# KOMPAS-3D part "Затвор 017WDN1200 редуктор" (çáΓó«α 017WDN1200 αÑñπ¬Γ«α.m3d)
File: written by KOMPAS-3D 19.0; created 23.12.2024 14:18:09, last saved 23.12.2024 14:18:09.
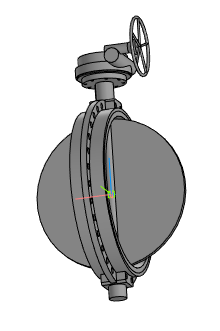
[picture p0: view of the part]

Document properties: Автор: Евгений; Полное имя файла: ..\Затвор 017WDN1200 редуктор.a3d

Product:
- Part/product: Затвор 017WDN1200 редуктор
    Масса: 1322.42

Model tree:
1. Операция без истории:1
